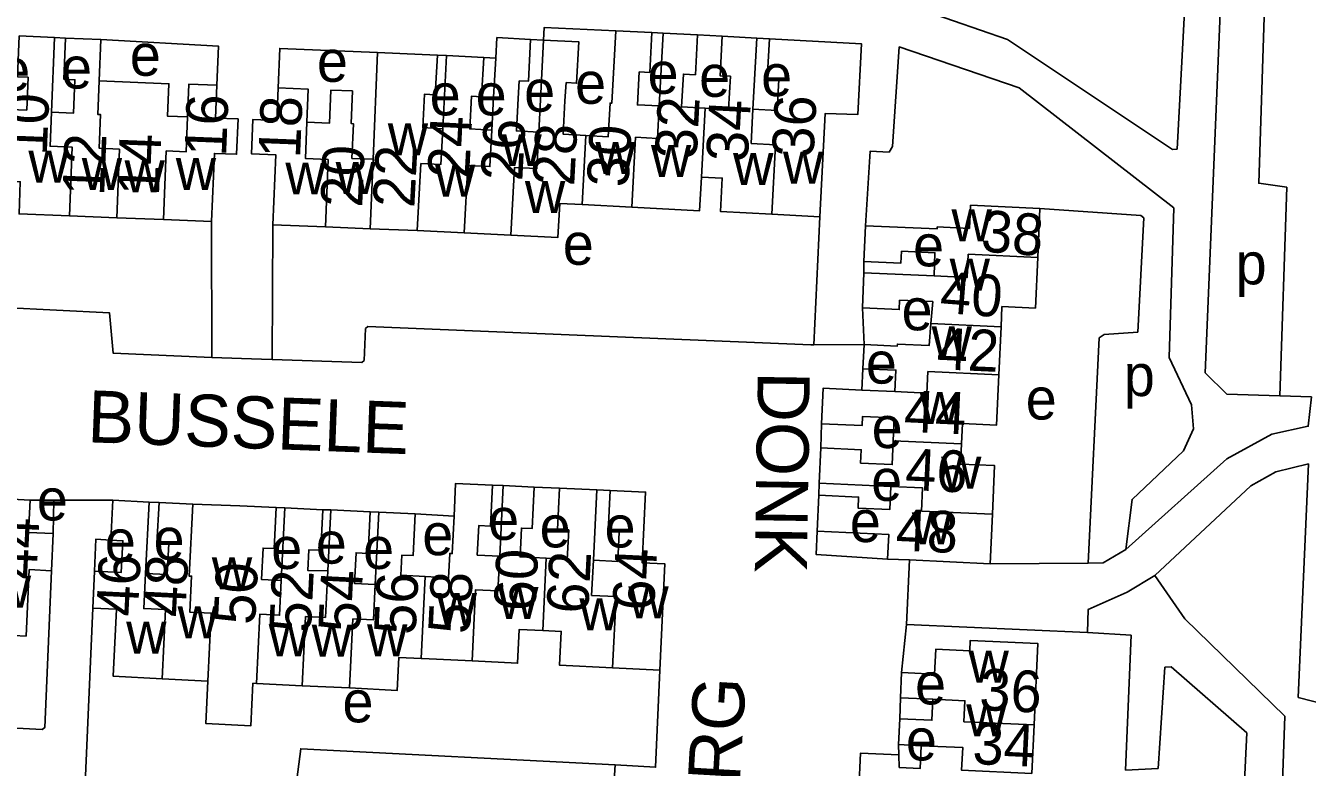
# Model space of a CAD drawing. Extents: x 163026 to 166241, y 382475 to 384501.
# Drawn here: x 164462 to 164584.9, y 383833.2 to 383904.4 of the extents above; entities that cross this region are included whole.
import ezdxf

# ---------------------------------------------------------------- set-up
doc = ezdxf.new("R2010")
doc.units = 0
for name, color, linetype in [('BLT_Basislijn', 7, 'Continuous'), ('BLT_Bebouwing', 7, 'Continuous'), ('BLT_Centroide', 7, 'Continuous'), ('BLT_Huisnummer', 7, 'Continuous'), ('BLT_Huisnummer_ tussenligend', 7, 'Continuous'), ('BLT_Onderverdeling_panden', 7, 'Continuous'), ('BLT_Straatnaam', 7, 'Continuous')]:
    doc.layers.add(name, color=color, linetype=linetype)

msp = doc.modelspace()

# ---------------------------------------------------------------- linework, layer by layer
at = {"layer": 'BLT_Basislijn'}
for p, q in [((164464.71, 383903.29), (164465.79, 383903.22)), ((164523.11, 383903.69), (164522.04, 383903.75)), ((164528.78, 383903.39), (164526.41, 383903.52)), ((164533.31, 383903.15), (164532.11, 383903.21)), ((164502.34, 383901.54), (164501.46, 383901.57)), ((164479.8, 383885.6), (164479.82, 383872.56)), ((164538.16, 383886.07), (164537.57, 383873.77)), ((164485.68, 383885.29), (164485.6, 383872.36)), ((164542.39, 383880.69), (164542.37, 383881.78)), ((164542.4, 383873.79), (164542.24, 383877.31)), ((164542.4, 383873.79), (164537.57, 383873.77)), ((164542.29, 383871.47), (164542.19, 383869.42)), ((164585.34, 383868.78), (164582.29, 383868.85)), ((164538.3, 383866.19), (164538.24, 383863.87)), ((164506.73, 383860.29), (164507.77, 383860.25)), ((164510.73, 383860.1), (164513.17, 383860.01)), ((164516.76, 383859.83), (164518.03, 383859.79)), ((164538.09, 383860.48), (164538.06, 383859.31)), ((164464.66, 383858.85), (164462.4, 383858.86)), ((164464.6, 383855.64), (164464.66, 383858.85)), ((164470.32, 383858.83), (164464.66, 383858.85)), ((164473.8, 383858.66), (164474.75, 383858.63)), ((164485.99, 383858.13), (164486.82, 383858.1)), ((164490.48, 383857.92), (164491.23, 383857.91)), ((164495.01, 383857.72), (164495.83, 383857.7)), ((164499.32, 383857.52), (164503.06, 383857.31)), ((164546.75, 383853.1), (164546.47, 383846.89)), ((164563.91, 383852.81), (164554.49, 383852.74)), ((164546.47, 383846.89), (164545.99, 383842.3)), ((164546.47, 383846.89), (164563.83, 383846.13)), ((164545.88, 383839.87), (164545.82, 383837.85)), ((164545.7, 383835.37), (164545.73, 383834.38)), ((164518.51, 383833.44), (164518.21, 383828.26))]:
    msp.add_line(p, q, dxfattribs=at)
for points in [[(164582.29, 383868.85), (164577.21, 383869.04), (164575.13, 383871.08), (164576.98, 383915.64), (164570.51, 383923.51), (164567.96, 383948.37), (164564.49, 383956.94), (164564.09, 383969.26), (164583.36, 383970.04), (164598.4, 383974.57), (164606.16, 383969.43), (164611.03, 383968.95), (164610.75, 383965.24)], [(164535.52, 383970), (164559.63, 383969.49), (164560.98, 383950.52), (164564.04, 383947), (164567.37, 383920.9), (164573.54, 383912.99), (164572.43, 383892.56), (164571.98, 383892.52), (164556.17, 383903.07), (164545.81, 383906.67), (164507.25, 383908.37), (164494.55, 383916.12), (164486.38, 383921.6), (164482.39, 383926.7), (164481.28, 383929.25), (164481.56, 383938.35), (164481.34, 383939)], [(164587.71, 383966.34), (164578.1, 383966.85), (164575.8, 383924.07), (164581.13, 383923.51), (164581.36, 383923.22), (164580.27, 383889.28), (164582.96, 383888.9), (164582.29, 383868.85)], [(164518.58, 383903.93), (164511.71, 383904.24), (164511.64, 383903.03)], [(164469.18, 383903.08), (164480.46, 383902.44), (164480.31, 383898.7)], [(164495.71, 383901.82), (164486.34, 383902.23), (164486.18, 383898.43)], [(164507.07, 383901.29), (164505.9, 383901.35)], [(164542.52, 383885.2), (164542.98, 383892.36), (164544.79, 383892.28), (164545.14, 383892.81), (164545.78, 383902.37), (164557.27, 383898.45), (164572.11, 383886.91), (164571.67, 383872.55), (164573.8, 383867.99), (164574.01, 383865.7), (164573.06, 383863.59), (164568.12, 383858.91), (164567.51, 383854.12)], [(164433.31, 383888.89), (164433.31, 383886.06), (164438.41, 383880.17), (164441.95, 383877.44), (164448.34, 383873.59), (164449, 383873.6), (164449.2, 383873.91), (164449.63, 383877.86), (164469.99, 383876.85), (164470.36, 383872.96), (164479.82, 383872.56)], [(164559.27, 383886.86), (164568.96, 383886.19), (164569.24, 383885.95), (164568.65, 383874.99), (164565.44, 383874.76), (164564.94, 383874.43), (164563.91, 383852.81)], [(164537.57, 383873.77), (164537.29, 383873.77), (164494.8, 383875.51), (164494.57, 383875.32), (164494.44, 383872.26), (164494.2, 383872.07), (164485.6, 383872.36)], [(164479.82, 383872.56), (164484.57, 383872.39), (164485.6, 383872.36)], [(164585.34, 383868.78), (164585.01, 383865.94), (164581.51, 383865.19), (164577.21, 383862.8), (164567.51, 383854.12)], [(164570.31, 383851.6), (164579.5, 383860.22), (164581.92, 383861.57), (164585.03, 383862.35)], [(164585.03, 383862.35), (164584.06, 383839.91), (164586.67, 383839.21), (164586.7, 383838.18), (164585.59, 383805.59), (164585.81, 383805.34), (164591.13, 383804.95), (164589.12, 383751.22)], [(164537.9, 383855.88), (164537.8, 383853.63), (164544.66, 383853.19)], [(164468.56, 383852.03), (164468.68, 383855.1), (164470.13, 383855)], [(164567.51, 383854.12), (164565.35, 383852.82), (164563.91, 383852.81)], [(164464.42, 383852.07), (164463.79, 383837.01), (164463.54, 383836.82), (164419.08, 383839.16), (164418.29, 383838.93)], [(164563.83, 383846.13), (164563.9, 383848.35), (164567.65, 383850.01), (164570.31, 383851.6)], [(164589.12, 383751.22), (164582.46, 383750.07), (164582.1, 383750.55), (164582.15, 383753.46), (164586.67, 383793.22), (164581.39, 383799.24), (164582.78, 383838.1), (164573.16, 383847.44), (164570.31, 383851.6)], [(164468.39, 383848.48), (164467.63, 383830.9), (164487.65, 383829.56), (164488.35, 383834.97), (164518.51, 383833.44)], [(164567.48, 383832.91), (164568.01, 383845.87), (164563.83, 383846.13)], [(164518.51, 383833.44), (164522.39, 383833.19), (164522.79, 383842.53)], [(164567.48, 383832.91), (164570.61, 383833.09), (164571.26, 383842.8), (164571.85, 383842.83), (164579.12, 383836.5), (164577.25, 383797.24), (164583.1, 383790.77), (164582.73, 383787.14), (164578.16, 383749.72), (164563.76, 383746.63), (164557.99, 383746.91)]]:
    msp.add_lwpolyline(points, dxfattribs=at)
at = {"layer": 'BLT_Bebouwing'}
for p, q in [((164522.04, 383903.75), (164518.58, 383903.93)), ((164464.71, 383903.29), (164461.34, 383903.43)), ((164469.18, 383903.08), (164465.79, 383903.22)), ((164469.02, 383899.1), (164469.18, 383903.08)), ((164511.64, 383903.03), (164510.4, 383903.09)), ((164511.36, 383897.3), (164511.64, 383903.03)), ((164526.41, 383903.52), (164523.11, 383903.69)), ((164532.11, 383903.21), (164528.78, 383903.39)), ((164505.9, 383901.35), (164502.34, 383901.54)), ((164506.85, 383897.54), (164507.07, 383901.29)), ((164515.34, 383887.23), (164520.12, 383886.98)), ((164559.06, 383882.16), (164559.27, 383886.86)), ((164466.15, 383886.15), (164470.7, 383885.97)), ((164470.7, 383885.97), (164475.17, 383885.79)), ((164475.17, 383885.79), (164479.8, 383885.6)), ((164533.54, 383886.31), (164538.16, 383886.07)), ((164490.71, 383885.09), (164485.68, 383885.29)), ((164495.01, 383884.91), (164490.71, 383885.09)), ((164499.53, 383884.74), (164504.02, 383884.52)), ((164504.02, 383884.52), (164508.51, 383884.3)), ((164542.52, 383885.2), (164542.37, 383881.78)), ((164542.39, 383880.69), (164542.24, 383877.31)), ((164555.33, 383870.88), (164555.54, 383875.49)), ((164542.4, 383873.79), (164542.29, 383871.47)), ((164538.24, 383863.87), (164538.09, 383860.48)), ((164507.77, 383860.25), (164510.73, 383860.1)), ((164513.17, 383860.01), (164516.76, 383859.83)), ((164462.4, 383858.86), (164460.07, 383858.98)), ((164470.32, 383858.83), (164470.13, 383855)), ((164473.8, 383858.66), (164470.32, 383858.83)), ((164477.98, 383858.47), (164474.75, 383858.63)), ((164482.49, 383858.3), (164477.98, 383858.47)), ((164485.99, 383858.13), (164482.49, 383858.3)), ((164538.06, 383859.31), (164537.9, 383855.88)), ((164490.48, 383857.92), (164486.82, 383858.1)), ((164495.01, 383857.72), (164491.23, 383857.91)), ((164499.32, 383857.52), (164495.83, 383857.7)), ((164554.49, 383852.74), (164554.71, 383857.49)), ((164464.42, 383852.07), (164464.6, 383855.64)), ((164544.66, 383853.19), (164546.75, 383853.1)), ((164546.75, 383853.1), (164554.49, 383852.74)), ((164468.56, 383852.03), (164468.39, 383848.48)), ((164522.79, 383842.53), (164518.26, 383842.75)), ((164545.88, 383839.87), (164545.99, 383842.3)), ((164475.06, 383841.7), (164479.44, 383841.48)), ((164484.09, 383841.25), (164488.48, 383841.03)), ((164488.48, 383841.03), (164493.02, 383840.81)), ((164545.7, 383835.37), (164545.82, 383837.85)), ((164558.72, 383837.27), (164558.5, 383832.61)), ((164547.89, 383835.27), (164545.7, 383835.37))]:
    msp.add_line(p, q, dxfattribs=at)
for points in [[(164518.58, 383903.93), (164518.21, 383896.97), (164518.02, 383896.98), (164517.85, 383893.75), (164515.69, 383893.87)], [(164461.34, 383903.43), (164461.18, 383899.5), (164462.18, 383899.46), (164462.06, 383896.3), (164459.65, 383896.39)], [(164464.42, 383896.11), (164464.71, 383903.29)], [(164465.79, 383903.22), (164465.63, 383899.26), (164466.68, 383899.22), (164466.55, 383896.02), (164464.42, 383896.11)], [(164507.07, 383901.29), (164507.17, 383903.26), (164510.4, 383903.09)], [(164510.4, 383903.09), (164510.19, 383899.08), (164509.3, 383899.13)], [(164511.64, 383903.03), (164515.03, 383902.85), (164514.82, 383898.89), (164513.8, 383898.95)], [(164522.74, 383896.7), (164520.65, 383896.8), (164520.82, 383899.97), (164521.84, 383899.92), (164522.04, 383903.75)], [(164523.11, 383903.69), (164522.74, 383896.7)], [(164527.15, 383896.49), (164524.89, 383896.61), (164525.06, 383899.76), (164526.21, 383899.7), (164526.41, 383903.52)], [(164528.78, 383903.39), (164528.58, 383899.6), (164529.57, 383899.55), (164529.4, 383896.37), (164527.15, 383896.49)], [(164531.74, 383896.39), (164532.11, 383903.21)], [(164533.31, 383903.15), (164533.11, 383899.29), (164534.22, 383899.23), (164534.07, 383896.27), (164531.74, 383896.39)], [(164538.16, 383886.07), (164538.68, 383895.98), (164541.79, 383895.87), (164542.15, 383902.68), (164533.31, 383903.15)], [(164495.28, 383891.58), (164495.71, 383901.82)], [(164495.71, 383901.82), (164500, 383901.65), (164501.46, 383901.57)], [(164501.97, 383894.52), (164500.05, 383894.62), (164500.22, 383897.83), (164501.26, 383897.78), (164501.46, 383901.57)], [(164502.34, 383901.54), (164501.97, 383894.52)], [(164506.68, 383894.38), (164504.56, 383894.49), (164504.73, 383897.64), (164505.7, 383897.59), (164505.9, 383901.35)], [(164477.49, 383895.65), (164475.57, 383895.72), (164475.7, 383898.83), (164469.02, 383899.1)], [(164511.2, 383894.19), (164509.04, 383894.31), (164509.21, 383897.42), (164509.3, 383899.13)], [(164515.69, 383893.87), (164513.54, 383893.98), (164513.7, 383897.18), (164513.8, 383898.95)], [(164480.31, 383898.7), (164477.62, 383898.81), (164477.49, 383895.65)], [(164479.8, 383885.6), (164480.06, 383892.15), (164482.19, 383892.07), (164482.33, 383895.45), (164480.18, 383895.53), (164480.31, 383898.7)], [(164485.68, 383885.29), (164485.95, 383892.02), (164483.61, 383892.11), (164483.74, 383895.39), (164486.06, 383895.3), (164486.18, 383898.43)], [(164486.18, 383898.43), (164489.06, 383898.31), (164488.93, 383895.14)], [(164488.93, 383895.14), (164491.12, 383895.05), (164491.24, 383898.23), (164493.31, 383898.15), (164493.19, 383895.01), (164493.4, 383895), (164493.26, 383891.66), (164495.28, 383891.58)], [(164506.85, 383897.54), (164506.68, 383894.38)], [(164511.36, 383897.3), (164511.2, 383894.19)], [(164459.38, 383889.51), (164461.44, 383889.42), (164461.32, 383886.34), (164466.15, 383886.15)], [(164520.12, 383886.98), (164526.62, 383886.64), (164526.8, 383889.87)], [(164526.8, 383889.87), (164528.79, 383889.77), (164528.62, 383886.57), (164533.54, 383886.31)], [(164508.51, 383884.3), (164513.02, 383884.08), (164513.2, 383887.35), (164515.34, 383887.23)], [(164559.27, 383886.86), (164552.61, 383887.16), (164552.51, 383884.95), (164549.42, 383885.09), (164549.41, 383884.89), (164542.52, 383885.2)], [(164499.53, 383884.74), (164495.01, 383884.91)], [(164542.37, 383881.78), (164545.94, 383881.61), (164545.99, 383882.75), (164549.2, 383882.6), (164549.11, 383880.38)], [(164555.54, 383875.49), (164555.63, 383877.44), (164558.84, 383877.29), (164559.06, 383882.16)], [(164549.11, 383880.38), (164542.39, 383880.69)], [(164542.24, 383877.31), (164545.77, 383877.15), (164545.81, 383878.05), (164548.98, 383877.91), (164548.81, 383875.8)], [(164548.81, 383875.8), (164548.65, 383873.7), (164545.59, 383873.84), (164545.58, 383873.64), (164542.4, 383873.79)], [(164542.29, 383871.47), (164545.45, 383871.33), (164545.36, 383869.27)], [(164551.75, 383864.26), (164551.84, 383866.2), (164555.11, 383866.05), (164555.33, 383870.88)], [(164542.19, 383869.42), (164538.46, 383869.59), (164538.3, 383866.19)], [(164545.36, 383869.27), (164542.19, 383869.42)], [(164538.3, 383866.19), (164542.21, 383866.01), (164542.25, 383866.89), (164545.3, 383866.75), (164545.2, 383864.55)], [(164545.2, 383864.55), (164545.1, 383862.27), (164542.06, 383862.41), (164542.12, 383863.69), (164538.24, 383863.87)], [(164554.71, 383857.49), (164554.92, 383862.16), (164551.66, 383862.31), (164551.75, 383864.26)], [(164503.06, 383857.31), (164503.21, 383860.46), (164506.73, 383860.29)], [(164506.73, 383860.29), (164506.55, 383856.36), (164505.43, 383856.41), (164505.29, 383853.58), (164507.44, 383853.48)], [(164507.44, 383853.48), (164507.77, 383860.25)], [(164510.73, 383860.1), (164510.54, 383856.11), (164509.52, 383856.16), (164509.39, 383853.39), (164511.91, 383853.26)], [(164511.91, 383853.26), (164513.92, 383853.16), (164514.06, 383855.99), (164512.98, 383856.04), (164513.17, 383860.01)], [(164516.76, 383859.83), (164516.43, 383853.08)], [(164516.43, 383853.08), (164518.77, 383852.96), (164518.91, 383855.81), (164517.83, 383855.86), (164518.03, 383859.79)], [(164518.03, 383859.79), (164521.44, 383859.62), (164521.1, 383852.83), (164523.29, 383852.72), (164522.79, 383842.53)], [(164544.96, 383860.16), (164544.86, 383857.94), (164541.83, 383858.08), (164541.87, 383859.14), (164538.06, 383859.31)], [(164538.09, 383860.48), (164544.96, 383860.16)], [(164464.6, 383855.64), (164462.24, 383855.74), (164462.4, 383858.86)], [(164473.46, 383851.8), (164473.8, 383858.66)], [(164474.75, 383858.63), (164474.55, 383854.73), (164475.69, 383854.68), (164475.54, 383851.7), (164473.46, 383851.8)], [(164486.48, 383851.12), (164484.59, 383851.22), (164484.74, 383854.24), (164485.8, 383854.19), (164485.99, 383858.13)], [(164486.82, 383858.1), (164486.48, 383851.12)], [(164490.94, 383852.05), (164489.03, 383852.09), (164489.13, 383854.09), (164490.29, 383854.03), (164490.48, 383857.92)], [(164491.23, 383857.91), (164490.94, 383852.05)], [(164495.49, 383850.74), (164493.51, 383850.84), (164493.66, 383853.8), (164494.81, 383853.74), (164495.01, 383857.72)], [(164495.83, 383857.7), (164495.49, 383850.74)], [(164500.28, 383851.51), (164497.95, 383851.64), (164498.05, 383853.58), (164499.12, 383853.53), (164499.32, 383857.52)], [(164500.28, 383851.51), (164502.53, 383851.38), (164502.65, 383853.74), (164502.89, 383853.72), (164503.06, 383857.31)], [(164537.9, 383855.88), (164544.77, 383855.56), (164544.66, 383853.19)], [(164470.13, 383855), (164471.28, 383854.95), (164471.13, 383851.9), (164468.56, 383852.03)], [(164457.24, 383846.03), (164461.99, 383845.8), (164462.3, 383852.18), (164464.42, 383852.07)], [(164468.39, 383848.48), (164470.67, 383848.37), (164470.35, 383841.93), (164475.06, 383841.7)], [(164511.56, 383846.33), (164509.32, 383846.44), (164509.15, 383843.19), (164504.79, 383843.41)], [(164518.26, 383842.75), (164513.18, 383843), (164513.34, 383846.24), (164511.56, 383846.33)], [(164545.99, 383842.3), (164549.17, 383842.15), (164549.28, 383844.53), (164552.54, 383844.38), (164552.59, 383845.38), (164559.07, 383845.08), (164558.72, 383837.27)], [(164493.02, 383840.81), (164497.61, 383840.58), (164497.77, 383843.75), (164499.89, 383843.64)], [(164499.89, 383843.64), (164500, 383843.64), (164504.79, 383843.41)], [(164479.44, 383841.48), (164479.23, 383837.4), (164483.56, 383837.19), (164483.76, 383841.27), (164484.09, 383841.25)], [(164549.01, 383839.73), (164545.88, 383839.87)], [(164545.82, 383837.85), (164548.91, 383837.71), (164549.01, 383839.73)], [(164545.73, 383834.38), (164545.77, 383833.18), (164547.79, 383833.09), (164547.89, 383835.27)], [(164541.9, 383831.1), (164542.05, 383834.55), (164545.73, 383834.38)]]:
    msp.add_lwpolyline(points, dxfattribs=at)
at = {"layer": 'BLT_Onderverdeling_panden'}
for p, q in [((164527.15, 383896.49), (164526.8, 383889.87)), ((164515.69, 383893.87), (164515.34, 383887.23)), ((164470.96, 383892.56), (164470.7, 383885.97)), ((164495.28, 383891.58), (164495.01, 383884.91)), ((164548.81, 383875.8), (164555.54, 383875.49)), ((164551.75, 383864.26), (164545.2, 383864.55)), ((164511.56, 383846.33), (164511.91, 383853.26)), ((164500.28, 383851.51), (164499.89, 383843.64))]:
    msp.add_line(p, q, dxfattribs=at)
for points in [[(164470.96, 383892.56), (164469.01, 383892.64), (164469.14, 383895.87), (164468.89, 383895.88), (164469.02, 383899.1)], [(164522.74, 383896.7), (164522.58, 383893.58), (164520.48, 383893.69), (164520.12, 383886.98)], [(164464.42, 383896.11), (164464.29, 383892.83), (164466.42, 383892.74), (164466.15, 383886.15)], [(164477.49, 383895.65), (164477.36, 383892.31), (164475.44, 383892.38), (164475.17, 383885.79)], [(164531.74, 383896.39), (164531.57, 383893.1), (164533.89, 383892.98), (164533.54, 383886.31)], [(164488.93, 383895.14), (164488.8, 383891.66), (164490.97, 383891.56), (164490.71, 383885.09)], [(164501.97, 383894.52), (164501.79, 383891.09), (164499.87, 383891.17), (164499.53, 383884.74)], [(164506.68, 383894.38), (164506.49, 383890.88), (164504.37, 383890.97), (164504.02, 383884.52)], [(164511.2, 383894.19), (164511.01, 383890.68), (164508.85, 383890.78), (164508.51, 383884.3)], [(164549.11, 383880.38), (164552.29, 383880.24), (164552.39, 383882.46), (164559.06, 383882.16)], [(164545.36, 383869.27), (164548.43, 383869.13), (164548.53, 383871.19), (164555.33, 383870.88)], [(164544.96, 383860.16), (164548.01, 383860.02), (164547.91, 383857.8), (164554.71, 383857.49)], [(164477.98, 383858.47), (164477.64, 383851.56), (164477.88, 383851.55), (164477.71, 383848.08), (164479.76, 383847.98), (164479.44, 383841.48)], [(164507.44, 383853.48), (164507.27, 383850.14), (164505.12, 383850.24), (164504.79, 383843.41)], [(164516.43, 383853.08), (164516.26, 383849.7), (164518.6, 383849.59), (164518.26, 383842.75)], [(164473.46, 383851.8), (164473.29, 383848.44), (164475.38, 383848.34), (164475.06, 383841.7)], [(164486.48, 383851.12), (164486.32, 383847.79), (164484.42, 383847.89), (164484.09, 383841.25)], [(164490.94, 383852.05), (164490.72, 383847.58), (164488.81, 383847.67), (164488.48, 383841.03)], [(164495.49, 383850.74), (164495.32, 383847.35), (164493.35, 383847.45), (164493.02, 383840.81)], [(164549.01, 383839.73), (164552.07, 383839.59), (164551.98, 383837.57), (164558.72, 383837.27)], [(164547.89, 383835.27), (164551.86, 383835.1), (164551.76, 383832.91), (164558.5, 383832.61)]]:
    msp.add_lwpolyline(points, dxfattribs=at)

# ---------------------------------------------------------------- texts
at = {"layer": 'BLT_Centroide'}
for s, p in [('e', (164471.95, 383899.6)), ('e', (164465.35, 383898.37)), ('e', (164489.9, 383899.02)), ('e', (164459.42, 383898.18)), ('e', (164521.63, 383897.87)), ('e', (164526.57, 383897.58)), ('e', (164532.52, 383897.64)), ('e', (164500.72, 383895.8)), ('e', (164505.13, 383895.8)), ('e', (164509.78, 383896.15)), ('e', (164514.67, 383896.91)), ('w', (164496.7, 383891.96)), ('w', (164507.61, 383890.92)), ('w', (164516.62, 383890.17)), ('w', (164521.95, 383889.89)), ('w', (164462.21, 383889.35)), ('w', (164467.34, 383888.63)), ('w', (164471.44, 383888.42)), ('w', (164476.36, 383888.63)), ('w', (164529.83, 383889.1)), ('w', (164534.62, 383889.23)), ('w', (164486.87, 383888.2)), ('w', (164491.69, 383888.26)), ('w', (164501.23, 383888)), ('w', (164509.86, 383886.41)), ('w', (164550.79, 383883.69)), ('e', (164513.49, 383881.45)), ('e', (164547.1, 383881.3)), ('w', (164550.61, 383878.97)), ('p', (164578.05, 383879.57)), ('e', (164546, 383875.16)), ('w', (164548.88, 383872.47)), ('e', (164542.57, 383870.04)), ('p', (164567.32, 383868.84)), ('e', (164557.91, 383866.59)), ('w', (164547.73, 383866.17)), ('e', (164543.13, 383863.85)), ('w', (164549.79, 383859.95)), ('e', (164543.08, 383858.78)), ('e', (164463.03, 383856.9)), ('e', (164506.33, 383855.03)), ('e', (164511.27, 383854.31)), ('e', (164517.5, 383854.3)), ('e', (164541.03, 383854.82)), ('w', (164546.98, 383854.6)), ('e', (164469.55, 383852.96)), ('e', (164474.23, 383853.12)), ('e', (164489.79, 383852.75)), ('e', (164500.01, 383853.56)), ('e', (164485.52, 383852.24)), ('e', (164494.33, 383852.24)), ('w', (164479.82, 383850.27)), ('w', (164458.61, 383848.52)), ('w', (164501.39, 383846.86)), ('w', (164507.29, 383847.44)), ('w', (164519.78, 383847.5)), ('w', (164476.53, 383845.58)), ('w', (164515.08, 383846.35)), ('w', (164471.6, 383844.1)), ('w', (164485.28, 383843.84)), ('w', (164489.4, 383843.83)), ('w', (164494.71, 383843.84)), ('w', (164552.42, 383841.31)), ('e', (164547.29, 383839.23)), ('e', (164492.35, 383837.51)), ('w', (164552.2, 383836.16)), ('e', (164546.41, 383833.85))]:
    msp.add_text(s, height=4, dxfattribs=at).set_placement(p)
at = {"layer": 'BLT_Huisnummer'}
for s, rotation, p in [('10', 87.7125, (164463.98, 383891.9)), ('16', 87.7108, (164481.18, 383891.8)), ('18', 87.6961, (164488.28, 383891.64)), ('36', 86.9866, (164537.54, 383891.69)), ('26', 86.9866, (164509.6, 383889.44)), ('30', 86.9866, (164519.78, 383888.84)), ('22', 86.9866, (164499.24, 383886.87)), ('38', 355.5054, (164553.53, 383882.74)), ('42', 357.3856, (164549.32, 383871.43)), ('48', 357.3784, (164545.38, 383854.03)), ('44', 87.1739, (164462.98, 383851.17)), ('46', 87.1743, (164472.71, 383847.62)), ('64', 87.1754, (164522.25, 383848.18)), ('50', 87.1849, (164483.96, 383846.83)), ('54', 87.163, (164494.02, 383846.1)), ('58', 87.1758, (164504.56, 383845.94)), ('36', 357.3662, (164553.41, 383838.7))]:
    msp.add_text(s, height=4, rotation=rotation, dxfattribs=at).set_placement(p)
at = {"layer": 'BLT_Huisnummer_ tussenligend'}
for s, rotation, p in [('32', 86.9866, (164526.32, 383891.54)), ('34', 86.9866, (164531.23, 383891.27)), ('24', 86.9866, (164504.49, 383889.7)), ('28', 86.9866, (164514.58, 383888.96)), ('12', 87.7125, (164469.48, 383888.03)), ('14', 87.7125, (164474.74, 383888.02)), ('20', 87.6961, (164494.24, 383886.91)), ('40', 355.5054, (164549.59, 383876.86)), ('44', 357.3856, (164546.17, 383865.43)), ('46', 357.3856, (164546.29, 383859.84)), ('60', 87.1758, (164510.85, 383848.12)), ('62', 87.1758, (164515.92, 383847.89)), ('48', 87.1743, (164477.27, 383847.56)), ('52', 87.1849, (164489.31, 383846.09)), ('56', 87.163, (164499.36, 383845.86)), ('34', 357.2917, (164552.75, 383833.52))]:
    msp.add_text(s, height=4, rotation=rotation, dxfattribs=at).set_placement(p)
at = {"layer": 'BLT_Straatnaam'}
for s, rotation, p in [('DONK', 269.1402, (164532.2, 383871.23)), ('BUSSELE', 357.8649, (164467.83, 383864.41)), ('OUWENBERG', 86.6837, (164528.48, 383797.23))]:
    msp.add_text(s, height=5, rotation=rotation, dxfattribs=at).set_placement(p)

doc.saveas('drawing.dxf')
